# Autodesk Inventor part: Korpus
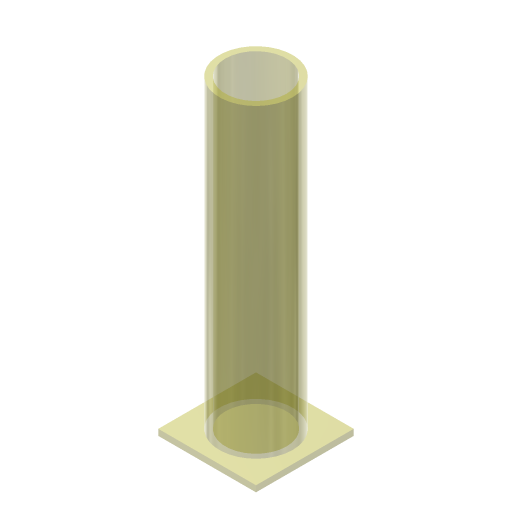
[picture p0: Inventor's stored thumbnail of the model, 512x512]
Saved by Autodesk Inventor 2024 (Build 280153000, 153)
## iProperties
Company: ATC
Created: 2023-03
Part Number: Korpus
Document SubType Name: Modeling
Designer: Andrzej Jaskulski
Density: 7.87 g/cm^3
Mass: 15.871 g
Surface Area: 161.27 cm^2
Volume: 15.871 cm^3
Material: Stal węglowa
Stock Number: Korpus
Appearance: Stal
Checked By: A.J.
Engr Approved By: Andrzej Jaskulski
Mfg Approved By: Andrzej Jaskulski
Authority: A.J.
Title: A.J.: Kurs R2024-MEP
Author: Andrzej Jaskulski
Revision Number: 1/24
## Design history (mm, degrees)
sketch "Szkic1"
  geometry: L1 (-16, 16)-(16, 16); L2 (16, 16)-(16, -16); L3 (16, -16)-(-16, -16); L4 (-16, -16)-(-16, 16); C1 r 10 at (0, 0); C2 r 12 at (0, 0); 2 further points
  constraints: 8 end point, 2 centre point, 2 midpoint, 2 parallel, 2 perpendicular, 1 coincident, 1 horizontal, 1 horizontal alignment, 1 vertical alignment, 1 other
  dimensions: "d0" = 20 diameter of C1; "d1" = 24 diameter of C2; "d6" = 32 distance of L2.end L3.end (computed from d1)
extrude "Wyciągnięcie proste1" new body sketch "Szkic1" distance "d2" = 100; taper "d3" = 0 deg
extrude "Wyciągnięcie proste2" join sketch "Szkic1" distance "d4" = 2; taper "d5" = 0 deg
extrude "Wyciągnięcie proste3" join sketch "Szkic1" distance "d7" = 2; taper "d8" = 0 deg
node "Bryła1"
node "Korpusy bryłowe"
node "Korpusy powierzchniowe"
